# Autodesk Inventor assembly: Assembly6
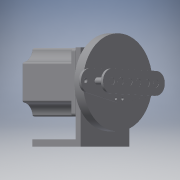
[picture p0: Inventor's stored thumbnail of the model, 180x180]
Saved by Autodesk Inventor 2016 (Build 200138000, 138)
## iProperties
Created: 2016-02
Part Number: Assembly6
Document SubType Name: Assembly
Designer: Juha-Pekka
Author: Juha-Pekka
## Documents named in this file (3)
- C:\Users\Juha-Pekka\Desktop\Assignment2\Assembly6.iam
- C:\Users\Juha-Pekka\Desktop\Assignment2\Assembly4.iam
- C:\Users\Juha-Pekka\Desktop\Assignment2\pickupbobbin.iam
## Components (2 placed, 2 different names)
1. Assembly4:1 [sub-assembly]
2. pickupbobbin:1 [sub-assembly]
